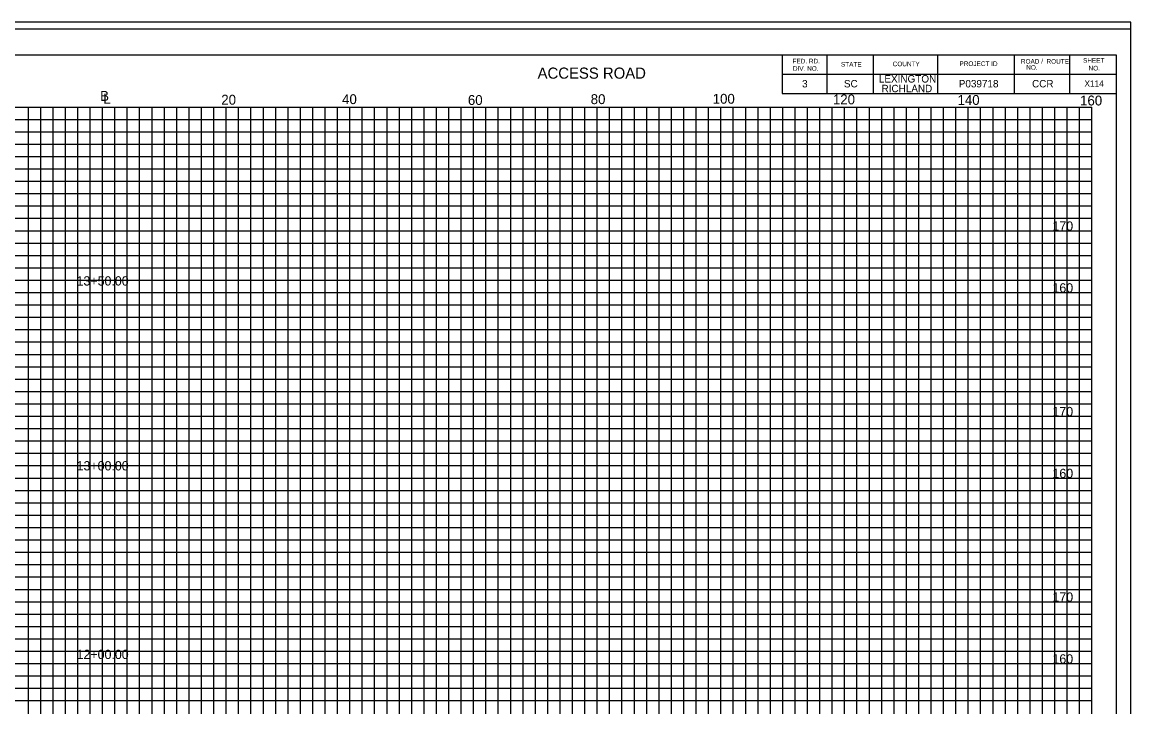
# Model space of a CAD drawing. Extents: x 967 to 1326, y 964 to 2864.
# Drawn here: x 1147 to 1326.3, y 1073 to 1183.7 of the extents above; entities that cross this region are included whole.
import ezdxf

# ---------------------------------------------------------------- set-up
doc = ezdxf.new("R2010")
doc.units = 0
for name, color, linetype in [('Default', 7, 'Continuous'), ('RD_EX_RW', 7, 'Continuous'), ('RD_PD_Final_TX', 7, 'Continuous'), ('RD_SHT_ShtClip', 7, 'Continuous'), ('RD_XS_TX_Elev_PR', 7, 'Continuous'), ('RD_XS_TX_Slope', 7, 'Continuous')]:
    doc.layers.add(name, color=color, linetype=linetype)

msp = doc.modelspace()

# ---------------------------------------------------------------- linework, layer by layer
at = {"layer": 'RD_EX_RW'}
for p, q in [((1000, 1170), (1320, 1170)), ((1150, 1000), (1150, 1170)), ((1160, 1000), (1160, 1170)), ((1170, 1000), (1170, 1170)), ((1180, 1000), (1180, 1170)), ((1190, 1000), (1190, 1170)), ((1200, 1000), (1200, 1170)), ((1210, 1000), (1210, 1170)), ((1220, 1000), (1220, 1170)), ((1230, 1000), (1230, 1170)), ((1240, 1000), (1240, 1170)), ((1250, 1000), (1250, 1170)), ((1260, 1000), (1260, 1170)), ((1270, 1000), (1270, 1170)), ((1280, 1000), (1280, 1170)), ((1290, 1000), (1290, 1170)), ((1300, 1000), (1300, 1170)), ((1310, 1000), (1310, 1170)), ((1320, 1000), (1320, 1170)), ((1000, 1160), (1320, 1160)), ((1000, 1150), (1320, 1150)), ((1000, 1140), (1320, 1140)), ((1000, 1130), (1320, 1130)), ((1000, 1120), (1320, 1120)), ((1000, 1110), (1320, 1110)), ((1000, 1100), (1320, 1100)), ((1000, 1090), (1320, 1090)), ((1000, 1080), (1320, 1080))]:
    msp.add_line(p, q, dxfattribs=at)
at = {"layer": 'RD_PD_Final_TX'}
for p, q in [((996.11, 1178.46), (1323.89, 1178.46)), ((1269.89, 1178.46), (1269.89, 1172.21)), ((1277.14, 1178.46), (1277.14, 1172.21)), ((1284.64, 1178.46), (1284.64, 1172.21)), ((1295, 1178.46), (1295, 1172.21)), ((1307.43, 1178.46), (1307.43, 1172.21)), ((1316.39, 1178.46), (1316.39, 1172.21)), ((1323.89, 1178.46), (1323.89, 968.98)), ((1269.89, 1175.33), (1323.89, 1175.33)), ((1269.89, 1172.21), (1323.89, 1172.21))]:
    msp.add_line(p, q, dxfattribs=at)
at = {"layer": 'RD_SHT_ShtClip'}
for p, q in [((1148, 1000), (1148, 1170)), ((1152, 1000), (1152, 1170)), ((1154, 1000), (1154, 1170)), ((1156, 1000), (1156, 1170)), ((1158, 1000), (1158, 1170)), ((1162, 1000), (1162, 1170)), ((1164, 1000), (1164, 1170)), ((1166, 1000), (1166, 1170)), ((1168, 1000), (1168, 1170)), ((1172, 1000), (1172, 1170)), ((1174, 1000), (1174, 1170)), ((1176, 1000), (1176, 1170)), ((1178, 1000), (1178, 1170)), ((1182, 1000), (1182, 1170)), ((1184, 1000), (1184, 1170)), ((1186, 1000), (1186, 1170)), ((1188, 1000), (1188, 1170)), ((1192, 1000), (1192, 1170)), ((1194, 1000), (1194, 1170)), ((1196, 1000), (1196, 1170)), ((1198, 1000), (1198, 1170)), ((1202, 1000), (1202, 1170)), ((1204, 1000), (1204, 1170)), ((1206, 1000), (1206, 1170)), ((1208, 1000), (1208, 1170)), ((1212, 1000), (1212, 1170)), ((1214, 1000), (1214, 1170)), ((1216, 1000), (1216, 1170)), ((1218, 1000), (1218, 1170)), ((1222, 1000), (1222, 1170)), ((1224, 1000), (1224, 1170)), ((1226, 1000), (1226, 1170)), ((1228, 1000), (1228, 1170)), ((1232, 1000), (1232, 1170)), ((1234, 1000), (1234, 1170)), ((1236, 1000), (1236, 1170)), ((1238, 1000), (1238, 1170)), ((1242, 1000), (1242, 1170)), ((1244, 1000), (1244, 1170)), ((1246, 1000), (1246, 1170)), ((1248, 1000), (1248, 1170)), ((1252, 1000), (1252, 1170)), ((1254, 1000), (1254, 1170)), ((1256, 1000), (1256, 1170)), ((1258, 1000), (1258, 1170)), ((1262, 1000), (1262, 1170)), ((1264, 1000), (1264, 1170)), ((1266, 1000), (1266, 1170)), ((1268, 1000), (1268, 1170)), ((1272, 1000), (1272, 1170)), ((1274, 1000), (1274, 1170)), ((1276, 1000), (1276, 1170)), ((1278, 1000), (1278, 1170)), ((1282, 1000), (1282, 1170)), ((1284, 1000), (1284, 1170)), ((1286, 1000), (1286, 1170)), ((1288, 1000), (1288, 1170)), ((1292, 1000), (1292, 1170)), ((1294, 1000), (1294, 1170)), ((1296, 1000), (1296, 1170)), ((1298, 1000), (1298, 1170)), ((1302, 1000), (1302, 1170)), ((1304, 1000), (1304, 1170)), ((1306, 1000), (1306, 1170)), ((1308, 1000), (1308, 1170)), ((1312, 1000), (1312, 1170)), ((1314, 1000), (1314, 1170)), ((1316, 1000), (1316, 1170)), ((1318, 1000), (1318, 1170)), ((1000, 1168), (1320, 1168)), ((1000, 1166), (1320, 1166)), ((1000, 1164), (1320, 1164)), ((1000, 1162), (1320, 1162)), ((1000, 1158), (1320, 1158)), ((1000, 1156), (1320, 1156)), ((1000, 1154), (1320, 1154)), ((1000, 1152), (1320, 1152)), ((1000, 1148), (1320, 1148)), ((1000, 1146), (1320, 1146)), ((1000, 1144), (1320, 1144)), ((1000, 1142), (1320, 1142)), ((1000, 1138), (1320, 1138)), ((1000, 1136), (1320, 1136)), ((1000, 1134), (1320, 1134)), ((1000, 1132), (1320, 1132)), ((1000, 1128), (1320, 1128)), ((1000, 1126), (1320, 1126)), ((1000, 1124), (1320, 1124)), ((1000, 1122), (1320, 1122)), ((1000, 1118), (1320, 1118)), ((1000, 1116), (1320, 1116)), ((1000, 1114), (1320, 1114)), ((1000, 1112), (1320, 1112)), ((1000, 1108), (1320, 1108)), ((1000, 1106), (1320, 1106)), ((1000, 1104), (1320, 1104)), ((1000, 1102), (1320, 1102)), ((1000, 1098), (1320, 1098)), ((1000, 1096), (1320, 1096)), ((1000, 1094), (1320, 1094)), ((1000, 1092), (1320, 1092)), ((1000, 1088), (1320, 1088)), ((1000, 1086), (1320, 1086)), ((1000, 1084), (1320, 1084)), ((1000, 1082), (1320, 1082)), ((1000, 1078), (1320, 1078)), ((1000, 1076), (1320, 1076)), ((1000, 1074), (1320, 1074))]:
    msp.add_line(p, q, dxfattribs=at)
at = {"layer": 'RD_XS_TX_Elev_PR'}
for points in [[(967.41, 963.72), (1326.28, 963.72), (1326.28, 1183.72), (967.41, 1183.72)], [(988.52, 964.84), (1326.28, 964.84), (1326.28, 1182.6), (988.52, 1182.6)]]:
    msp.add_lwpolyline(points, close=True, dxfattribs=at)

# ---------------------------------------------------------------- texts
at = {"layer": 'Default'}
for s, height, p in [('X114', 1, (1318.79, 1173.3)), ('170', 1.5, (1313.61, 1150)), ('13+50.00', 1.5, (1155.8, 1141.13)), ('160', 1.5, (1313.61, 1140)), ('170', 1.5, (1313.61, 1120)), ('13+00.00', 1.5, (1155.8, 1111.23)), ('160', 1.5, (1313.61, 1110)), ('170', 1.5, (1313.61, 1090)), ('12+00.00', 1.5, (1155.8, 1080.73)), ('160', 1.5, (1313.61, 1080))]:
    msp.add_text(s, height=height, dxfattribs=at).set_placement(p)
at = {"layer": 'RD_XS_TX_Slope'}
for s, height, p in [('SHEET', 0.75, (1318.56, 1177.16)), ('FED. RD.', 0.75, (1271.58, 1177.05)), ('DIV. NO.', 0.75, (1271.64, 1175.86)), ('STATE', 0.75, (1279.41, 1176.53)), ('COUNTY', 0.75, (1287.78, 1176.59)), ('PROJECT ID', 0.75, (1298.58, 1176.63)), ('ROAD /  ROUTE', 0.75, (1308.51, 1177.01)), ('   NO.', 0.75, (1308.51, 1176.03)), ('NO.', 0.75, (1319.45, 1175.91)), ('3', 1.2, (1273.12, 1173.17)), ('SC', 1.2, (1279.89, 1173.17)), ('LEXINGTON', 1.2, (1285.54, 1173.96)), ('P039718', 1.2, (1298.46, 1173.17)), ('CCR', 1.2, (1310.31, 1173.17)), ('B', 1.6, (1159.61, 1170.99)), ('RICHLAND', 1.2, (1285.97, 1172.39)), ('L', 1.6, (1160.12, 1170.54)), ('20', 1.6, (1179.2, 1170.38)), ('40', 1.6, (1198.74, 1170.47)), ('60', 1.6, (1219.08, 1170.33)), ('80', 1.6, (1238.94, 1170.47)), ('100', 1.6, (1258.67, 1170.53)), ('120', 1.6, (1278.11, 1170.43)), ('140', 1.6, (1298.26, 1170.34)), ('160', 1.6, (1318.08, 1170.25))]:
    msp.add_text(s, height=height, dxfattribs=at).set_placement(p)
msp.add_text('ACCESS ROAD', height=1.8, rotation=0, dxfattribs=at).set_placement((1230.35, 1174.58))

doc.saveas('drawing.dxf')
